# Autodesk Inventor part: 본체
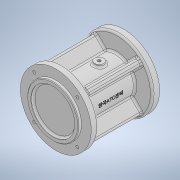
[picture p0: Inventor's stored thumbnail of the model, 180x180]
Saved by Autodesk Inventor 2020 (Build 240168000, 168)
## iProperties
Created: 2024-10
Part Number: 본체
Material: 일반
Document SubType Name: Modeling
Designer: oem
Density: 1 g/cm^3
Appearance: 기본값
Author: oem
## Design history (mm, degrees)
sketch "스케치1"
  geometry: C1 r 58 at (0, 0); 1 further point
  constraints: 1 centre point, 1 coincident
  dimensions: "d0" = 116 diameter of C1
extrude "돌출1" new body sketch "스케치1" distance "d1" = 12; taper "d2" = 0 deg
sketch "스케치2"
  geometry: C1 r 58 at (0, 0) reference; C2 r 30 at (0, 0)
  constraints: 1 centre point, 1 coincident
  dimensions: "d3" = 60 diameter of C2
extrude "돌출2" join sketch "스케치2" distance "d4" = 88; taper "d5" = 0 deg
sketch "스케치3"
  geometry: C1 r 30 at (0, 0) reference; C2 r 58 at (0, 0)
  constraints: 1 centre point, 1 coincident
  dimensions: "d6" = 116 diameter of C2
extrude "돌출3" join sketch "스케치3" distance "d7" = 12; taper "d8" = 0 deg
sketch "스케치4"
  geometry: C1 r 58 at (0, 0) reference; C2 r 42 at (0, 0)
  constraints: 1 centre point, 1 coincident
  dimensions: "d9" = 84 diameter of C2
extrude "돌출4" join sketch "스케치4" distance "d10" = 5; taper "d11" = 0 deg
sketch "스케치5"
  geometry: C1 r 58 at (0, 0) reference; C2 r 42 at (0, 0)
  constraints: 1 centre point, 1 coincident
  dimensions: "d12" = 84 diameter of C2
extrude "돌출5" join sketch "스케치5" distance "d13" = 5; taper "d14" = 0 deg
sketch "스케치7"
  geometry: L1 (58, 12)-(58, 0) reference; L2 (58, 0)-(42, 0) reference; L3 (42, 0)-(42, -5) reference; L4 (42, -5)-(-42, -5) reference; L5 (-42, -5)-(-42, 0) reference; L6 (-42, 0)-(-58, 0) reference; L7 (-58, 0)-(-58, 12) reference; L8 (-58, 12)-(-30, 12) reference; L9 (-30, 12)-(-30, 100) reference; L10 (-30, 100)-(-58, 100) reference; L11 (-58, 100)-(-58, 112) reference; L12 (-58, 112)-(-42, 112) reference; L13 (-42, 112)-(-42, 117) reference; L14 (-42, 117)-(42, 117) reference; L15 (42, 117)-(42, 112) reference; L16 (42, 112)-(58, 112) reference; L17 (58, 112)-(58, 100) reference; L18 (58, 100)-(30, 100) reference; L19 (30, 100)-(30, 12) reference; L20 (30, 12)-(58, 12) reference; L21 (0, 138.748)-(0, -22.97); L22 (30, 100)-(-30, 100) reference; L23 (-30, 100)-(-23, 100); L24 (-30, 100)-(-30, 85); L25 (-30, 12)-(-30, 100) reference; L26 (-30, 85)-(-23, 85); L27 (-23, 85)-(-23, 100); L28 (-23, 85)-(0, 85); L29 (-23, 100)-(0, 100); 1 further point
  constraints: 14 end point, 2 horizontal, 2 point on line, 2 vertical, 1 midpoint
  dimensions: "d24" = 15 distance of L26.end L23.end; "d25" = 46 diameter of L27 L21; "d26" = 30 distance from line of L19 L21.end
revolve "회전1" sketch "스케치7" stored, may be unused: angle "d27" = 90 deg
sketch "스케치8"
  geometry: L1 (0, 0)-(77.91, 0); L2 (0, 0)-(38.184, -38.184); L3 (34.648, -41.719)-(-12.071, 5); L4 (41.719, -34.648)-(-5, 12.071); L5 (34.648, -41.719)-(41.719, -34.648); L6 (-12.071, 5)-(-5, 12.071); C1 r 23 at (0, 0) reference; C2 r 58 at (0, 0) reference
  constraints: 12 end point, 1 horizontal
  dimensions: "d28" = 45 deg angle of L1 L2; "d29" = 54 distance of L1.start L2.end; "d30" = 5 distance between parallel lines of L2 L3; "d31" = 5 distance between parallel lines of L2 L4
extrude "돌출7" join sketch "스케치8" stored distance "d32" = 5; taper "d33" = 0 deg
sketch "스케치9"
  geometry: L1 (42, 117)-(42, 112) reference; L2 (42, 112)-(58, 112) reference; L3 (58, 112)-(58, 100) reference; L4 (58, 100)-(23, 100) reference; L5 (23, 100)-(23, 85) reference; L6 (23, 85)-(30, 85) reference; L7 (30, 85)-(30, 12) reference; L8 (30, 12)-(58, 12) reference; L9 (58, 12)-(58, 0) reference; L10 (58, 0)-(42, 0) reference; L11 (42, 0)-(42, -5) reference; L12 (42, -5)-(-42, -5) reference; L13 (-42, -5)-(-42, 0) reference; L14 (-42, 0)-(-58, 0) reference; L15 (-58, 0)-(-58, 12) reference; L16 (-58, 12)-(-30, 12) reference; L17 (-30, 12)-(-30, 85) reference; L18 (-30, 85)-(-23, 85) reference; L19 (-23, 85)-(-23, 100) reference; L20 (-23, 100)-(-58, 100) reference; L21 (-58, 100)-(-58, 112) reference; L22 (-58, 112)-(-42, 112) reference; L23 (-42, 112)-(-42, 117) reference; L24 (-42, 117)-(42, 117) reference; C1 r 7.5 at (0, 41); 1 further point
  constraints: 1 centre point, 1 vertical alignment
  dimensions: "d37" = 15 diameter of C1; "d38" = 29 distance from line of L16 C1.centre
extrude "돌출8" join sketch "스케치9" stored distance "d39" = 68; taper "d40" = 0 deg
sketch "스케치11"
  geometry: C1 r 42 at (0, 0) reference; 2 further points
  constraints: 1 coincident
hole "구멍1" sketch "스케치11" at (0, 0) diameter "d41" = 72; stored, may be unused: countersink angle "d45" = 90 deg, drill point angle "d47" = 0 deg; dims "d42" = 6, "d43" = 4, "d44" = 2, "d46" = 3
sketch "스케치12"
  geometry: L1 (-42, 112)-(-42, 117) reference; L2 (-42, 117)-(42, 117) reference; L3 (42, 117)-(42, 112) reference; L4 (42, 112)-(58, 112) reference; L5 (58, 112)-(58, 100) reference; L6 (58, 100)-(23, 100) reference; L7 (23, 100)-(23, 85) reference; L8 (23, 85)-(30, 85) reference; L9 (30, 85)-(30, 48.5) reference; L10 (30, 48.5)-(34, 48.5) reference; L11 (34, 48.5)-(34, 33.5) reference; L12 (34, 33.5)-(30, 33.5) reference; L13 (30, 33.5)-(30, 12) reference; L14 (30, 12)-(58, 12) reference; L15 (58, 12)-(58, 0) reference; L16 (58, 0)-(42, 0) reference; L17 (42, 0)-(42, -5) reference; L18 (42, -5)-(36, -5) reference; L19 (36, -5)-(36, -2) reference; L20 (36, -2)-(-36, -2) reference; L21 (-36, -2)-(-36, -5) reference; L22 (-36, -5)-(-42, -5) reference; L23 (-42, -5)-(-42, 0) reference; L24 (-42, 0)-(-58, 0) reference; L25 (-58, 0)-(-58, 12) reference; L26 (-58, 12)-(-30, 12) reference; L27 (-30, 12)-(-30, 33.5) reference; L28 (-30, 33.5)-(-34, 33.5) reference; L29 (-34, 33.5)-(-34, 48.5) reference; L30 (-34, 48.5)-(-30, 48.5) reference; L31 (-30, 48.5)-(-30, 85) reference; L32 (-30, 85)-(-23, 85) reference; L33 (-23, 85)-(-23, 100) reference; L34 (-23, 100)-(-58, 100) reference; L35 (-58, 100)-(-58, 112) reference; L36 (-58, 112)-(-42, 112) reference; L37 (36, -5)-(-36, -5) reference; L38 (0, -5)-(0, 117); L39 (42, 117)-(-42, 117) reference; L40 (-36, -2)-(36, -2) reference; L41 (0, -2)-(21, -2); L42 (21, -2)-(21, 14); L43 (21, 14)-(25, 14); L44 (25, 14)-(25, 68); L45 (24.452, 12)-(24.452, 85) reference; L46 (25, 68)-(21, 68); L47 (21, 68)-(21, 80); L48 (21, 80)-(18, 80); L49 (18, 80)-(18, 98); L50 (18, 98)-(16, 98); L51 (16, 98)-(16, 102); L52 (16, 102)-(10.5, 102); L53 (10.5, 102)-(10.5, 105); L54 (10.5, 105)-(0, 105); 4 further points
  constraints: 28 end point, 9 perpendicular, 4 point on line, 3 midpoint, 1 parallel, 1 vertical
  dimensions: "d48" = 21 diameter of L53 L38; "d49" = 32 diameter of L51 L38; "d50" = 36 diameter of L49 L38; "d51" = 42 diameter of L47 L38; "d53" = 3 distance of L52.end L53.end; "d54" = 4 distance of L50.end L51.end; "d57" = 18 distance of L48.end L49.end; "d58" = 82 distance between parallel lines of L20 L48; "d59" = 54 distance between parallel lines of L43 L46; "d60" = 16 distance between parallel lines of L41 L43; "d153" = 50 diameter of L44 L38
revolve "회전2" sketch "스케치12" stored, may be unused: angle "d61" = 90 deg
sketch "스케치13"
  geometry: C1 r 42 at (0, 0) reference; 2 further points
  constraints: 1 coincident
hole "구멍2" sketch "스케치13" at (0, 0) diameter "d62" = 72; stored, may be unused: countersink angle "d66" = 90 deg, drill point angle "d68" = 0 deg; dims "d63" = 6, "d64" = 4, "d65" = 2, "d67" = 4
sketch "스케치14"
  geometry: C1 r 7.5 at (0, 0) reference; 2 further points
  constraints: 1 coincident
hole "구멍3" sketch "스케치14" at (0, 0) diameter "d69" = 5.1881; stored, may be unused: countersink angle "d73" = 90 deg, drill point angle "d75" = 0 deg; dims "d70" = 12, "d71" = 4, "d72" = 2, "d74" = 16
sketch "스케치16" dims "d88" = 56
  geometry: L1 (0, 0)-(0, -28); C1 r 21 at (0, 0) reference; C2 r 36 at (0, 0) reference; 4 further points
  constraints: 2 coincident, 2 end point, 1 vertical, 1 vertical alignment, 7 other
  dimensions: "d91" = 360 deg dimension on C1.centre point (0, -28) (derived)
hole "구멍5" sketch "스케치16" at (0, -28), (28, 0), (0, 28), (-28, 0) diameter "d93" = 4.134; stored, may be unused: countersink angle "d97" = 90 deg, drill point angle "d99" = 118 deg; dims "d94" = 10, "d95" = 4, "d96" = 2, "d98" = 12
sketch "스케치18"
  geometry: L1 (0, 0)-(0, -50); L2 (0, 0)-(-35.355, -35.355); C1 r 42 at (0, 0) reference; C2 r 58 at (0, 0) reference; C3 r 10.5 at (0, 0) reference; A1 r 50 centre (0, 0) between (0, -50) and (-35.355, -35.355); 4 further points
  constraints: 4 end point, 2 coincident, 2 point on circle, 1 centre point, 1 vertical, 5 other
  dimensions: "d112" = 100 diameter of A1; "d113" = 45 deg angle of L2 L1; "d116" = 360 deg dimension on C1.centre point (-35.355, -35.355) (derived)
hole "구멍7" sketch "스케치18" at (-35.355, -35.355), (35.355, -35.355), (35.355, 35.355), (-35.355, 35.355) diameter "d118" = 4.917; stored, may be unused: countersink angle "d122" = 90 deg, drill point angle "d124" = 118 deg; dims "d119" = 12, "d120" = 4, "d121" = 2, "d123" = 14
node "작업 평면1"
node "작업 평면2"
sketch "스케치19"
  geometry: L1 (3.002, 72.739)-(3.002, 31.261); L2 (3.002, 31.261)-(-3.002, 31.261); L3 (-3.002, 31.261)-(-3.002, 72.739); L4 (-3.002, 72.739)-(3.002, 72.739); L5 (3.002, 52)-(-3.002, 52); L6 (58, 0)-(-58, 0) reference; 2 further points
  constraints: 3 midpoint, 2 end point, 1 vertical alignment, 2 other
  dimensions: "d126" = 52 distance from line of L6 L5.end
feature "엠보싱1" sketch "스케치19" dims "d0" = 116, "d127" = 0.5, "d128" = 0
fillet "모깎기1" dims "d129" = 3
chamfer "모따기1" distance "d130" = 1; stored, may be unused: second distance "d131" = 2, angle "d132" = 45 deg
fillet "모깎기2" dims "d133" = 3
fillet "모깎기3" dims "d134" = 3
fillet "모깎기4" dims "d135" = 3
fillet "모깎기5" dims "d136" = 3
fillet "모깎기6" dims "d137" = 3
fillet "모깎기7" dims "d138" = 3
fillet "모깎기8" dims "d139" = 3
fillet "모깎기10" dims "d141" = 3
fillet "모깎기11" dims "d142" = 0.6
chamfer "모따기2" distance "d143" = 1; stored, may be unused: second distance "d144" = 2, angle "d145" = 45 deg
fillet "모깎기12" dims "d146" = 0.6
fillet "모깎기13" dims "d147" = 3
chamfer "모따기3" distance "d148" = 1; stored, may be unused: second distance "d149" = 2, angle "d150" = 45 deg
fillet "모깎기14" dims "d151" = 3
fillet "모깎기15" dims "d152" = 3
node "솔리드1"
pattern_circular "원형 패턴2" dims angle "d35" = 360 deg
mirror "미러1"
node "절단 모서리 투영2"
node "절단 모서리 투영3"
node "절단 모서리 투영4"
node "절단 모서리 투영6"
feature "A9D066F2-1C7D-4E18-AEED-F7BC21143FA4" dims "d41" = 72, "d42" = 6, "d43" = 4, "d44" = 2, "d45" = 90 deg, "d46" = 3, "d47" = 0
